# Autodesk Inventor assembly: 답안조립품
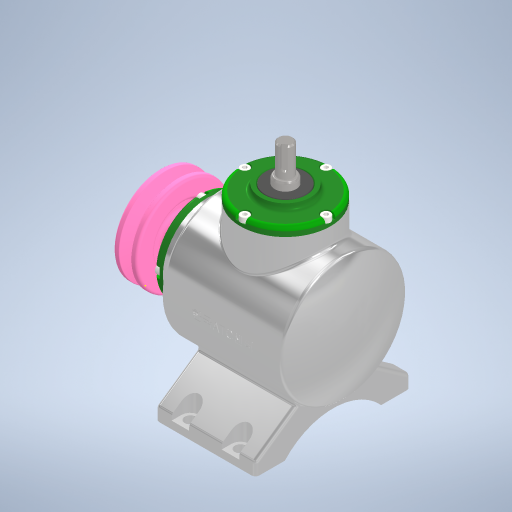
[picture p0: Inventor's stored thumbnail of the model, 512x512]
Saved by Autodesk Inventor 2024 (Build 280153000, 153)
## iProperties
Created: 2023-08
Part Number: 답안조립품
Document SubType Name: Assembly
Designer: Owner
Author: Owner
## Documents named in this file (17)
- C:\Users\Owner\Desktop\730813V1011\답안조립품.iam
- C:\Users\Owner\Desktop\730813V1011\본체.ipt
- C:\Users\Owner\Desktop\730813V1011\V-벨트풀리.ipt
- C:\Users\Owner\Desktop\730813V1011\메인 베벨기어.ipt
- C:\Users\Owner\Desktop\730813V1011\메인 축.ipt
- 메인 축.ipt
- C:\Users\Owner\Desktop\730813V1011\베어링 6203.ipt
- C:\Users\Owner\Desktop\730813V1011\볼트 M4 x 10.ipt
- C:\Users\Owner\Desktop\730813V1011\서브 베벨기어.ipt
- C:\Users\Owner\Desktop\730813V1011\서브 축.ipt
- 서브 축.ipt
- C:\Users\Owner\Desktop\730813V1011\오일실 17 x 32 x 8.ipt
- C:\Users\Owner\Desktop\730813V1011\와셔 4 x 16.ipt
- C:\Users\Owner\Desktop\730813V1011\육각볼트 M4 x 8.ipt
- C:\Users\Owner\Desktop\730813V1011\커버.ipt
- C:\Users\Owner\Desktop\730813V1011\키 4 x 4 x 14.ipt
- C:\Users\Owner\Desktop\730813V1011\키 5 x 5 x 14.ipt
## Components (1 placed, 1 different names)
1. V-벨트풀리:1 — 각도:1
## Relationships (1: Angle 1)
- 각도:1 [Angle]: V-벨트풀리:1
